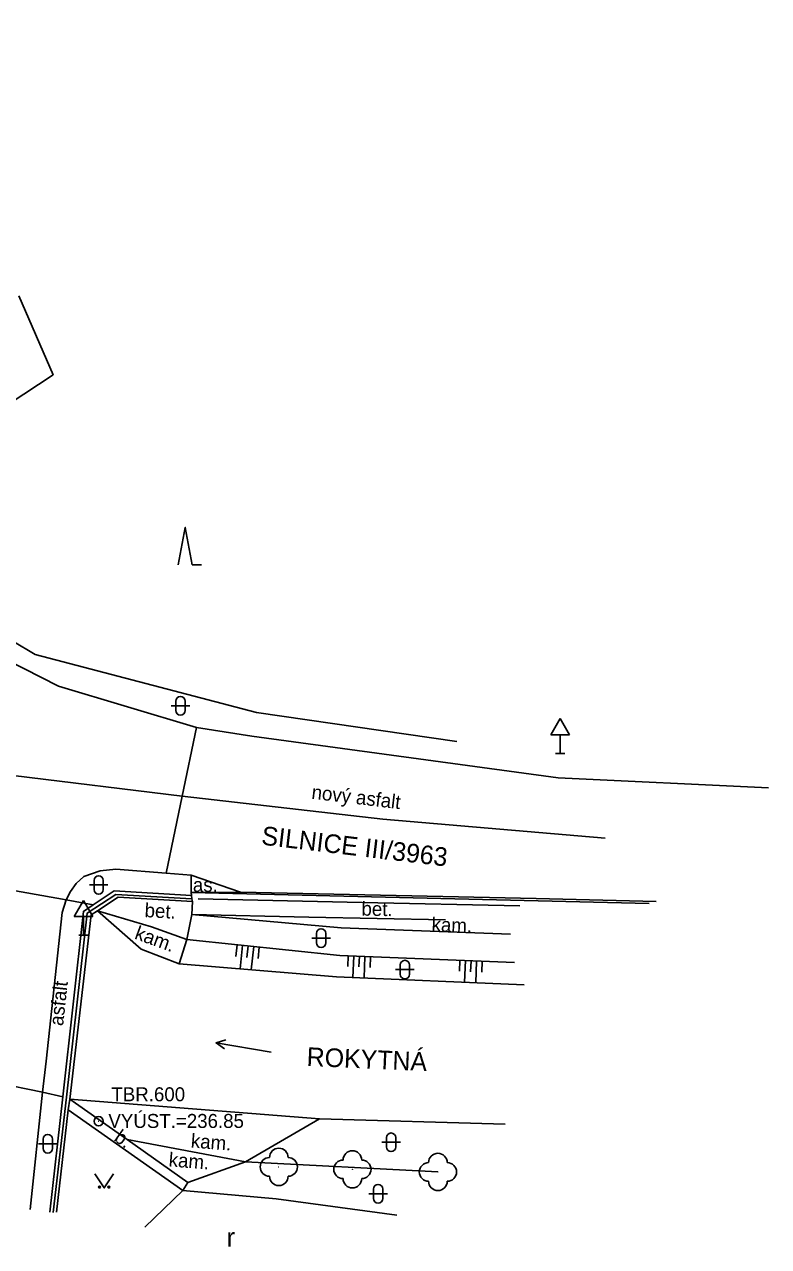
# Model space of a CAD drawing. Extents: x -621335 to -621199, y -1175437 to -1175180.
# Drawn here: x -621239.4 to -621199.5, y -1175433.3 to -1175367.7 of the extents above; entities that cross this region are included whole.
import ezdxf

# ---------------------------------------------------------------- set-up
doc = ezdxf.new("R2010")
doc.units = 0
for name, color, linetype in [('Budovy - zadní trakty', 7, 'Continuous'), ('Doplňkové značky', 7, 'Continuous'), ('Názvy', 7, 'Continuous'), ('Pomocné popisy', 7, 'Continuous'), ('Rozhraní ploch', 7, 'Continuous'), ('Výškopis', 7, 'Continuous'), ('Zeleň', 7, 'Continuous'), ('Značky kultur', 7, 'Continuous')]:
    doc.layers.add(name, color=color, linetype=linetype)

msp = doc.modelspace()

# ---------------------------------------------------------------- linework, layer by layer
at = {"layer": 'Budovy - zadní trakty'}
msp.add_lwpolyline([(-621247.56, -1175392.9), (-621247.26, -1175392.7), (-621237.86, -1175386.5), (-621239.7, -1175382.27)], dxfattribs=at)
at = {"layer": 'Doplňkové značky'}
for p, q in [((-621210.63, -1175404.944), (-621211.13, -1175405.81)), ((-621210.63, -1175404.944), (-621210.13, -1175405.81)), ((-621211.13, -1175405.81), (-621210.13, -1175405.81)), ((-621210.63, -1175406.81), (-621210.63, -1175405.81)), ((-621210.88, -1175406.81), (-621210.38, -1175406.81)), ((-621205.86, -1175414.86), (-621230.45, -1175414.28)), ((-621236.22, -1175414.694), (-621236.72, -1175415.56)), ((-621236.22, -1175414.694), (-621235.72, -1175415.56)), ((-621236.72, -1175415.56), (-621235.72, -1175415.56)), ((-621236.22, -1175416.56), (-621236.22, -1175415.56)), ((-621236.47, -1175416.56), (-621235.97, -1175416.56))]:
    msp.add_line(p, q, dxfattribs=at)
for points in [[(-621230.43, -1175414.44), (-621234.58, -1175414.18), (-621235.7, -1175414.93), (-621236.23, -1175415.29), (-621237.34, -1175425.23), (-621238.03, -1175431.41)], [(-621230.4, -1175414.62), (-621234.49, -1175414.38), (-621236.02, -1175415.38), (-621237.14, -1175425.25), (-621237.86, -1175431.43)], [(-621237.68, -1175431.42), (-621237.04, -1175425.93), (-621236.96, -1175425.35), (-621235.81, -1175415.47), (-621235.48, -1175415.26), (-621234.36, -1175414.53), (-621230.38, -1175414.75)], [(-621230.38, -1175414.75), (-621230.4, -1175414.62), (-621230.43, -1175414.44)], [(-621230.06, -1175414.62), (-621221.26, -1175414.8), (-621212.81, -1175414.98)], [(-621230.62, -1175429.83), (-621233.88, -1175427.52), (-621236.96, -1175425.35)], [(-621230.62, -1175429.83), (-621230.89, -1175430.26), (-621237.04, -1175425.93)]]:
    msp.add_lwpolyline(points, dxfattribs=at)
for radius in [0.25, 0.0005]:
    msp.add_circle((-621235.41, -1175426.54), radius, dxfattribs=at)
at = {"layer": 'Rozhraní ploch'}
for p, q in [((-621237.16, -1175414.66), (-621246.24, -1175413.05)), ((-621231.78, -1175413.24), (-621230.45, -1175413.35)), ((-621230.45, -1175413.35), (-621227.8, -1175414.26)), ((-621230.45, -1175414.28), (-621227.8, -1175414.26)), ((-621235.7, -1175414.93), (-621237.16, -1175414.66)), ((-621230.41, -1175415.46), (-621230.38, -1175414.75)), ((-621230.67, -1175416.8), (-621230.41, -1175415.46)), ((-621231.08, -1175418.1), (-621230.67, -1175416.8)), ((-621247.33, -1175423.15), (-621238.43, -1175424.99)), ((-621239.09, -1175431.27), (-621238.43, -1175424.99)), ((-621238.43, -1175424.99), (-621237.34, -1175425.23)), ((-621236.96, -1175425.35), (-621223.55, -1175426.41)), ((-621223.55, -1175426.41), (-621227.53, -1175428.72)), ((-621223.55, -1175426.41), (-621213.59, -1175426.69)), ((-621227.53, -1175428.72), (-621233.88, -1175427.52)), ((-621227.53, -1175428.72), (-621230.62, -1175429.83))]:
    msp.add_line(p, q, dxfattribs=at)
for points in [[(-621289.26, -1175328.38), (-621284.69, -1175342.49), (-621282.48, -1175348.71), (-621278.54, -1175359.18), (-621274.2, -1175369.3), (-621270.32, -1175376.95), (-621266.97, -1175382.2), (-621259.66, -1175391.26), (-621249.09, -1175401.63), (-621240, -1175407.99), (-621230.92, -1175409.11)], [(-621249.92, -1175395.65), (-621246.88, -1175398.47), (-621237.56, -1175403.21), (-621230.15, -1175405.43)], [(-621230.15, -1175405.43), (-621230.92, -1175409.11), (-621231.78, -1175413.24)], [(-621230.15, -1175405.43), (-621227.18, -1175405.88), (-621210.75, -1175408.13), (-621199.45, -1175408.65)], [(-621230.92, -1175409.11), (-621220.16, -1175410.34), (-621208.23, -1175411.36)], [(-621237.16, -1175414.66), (-621236.92, -1175414.21), (-621236.61, -1175413.79), (-621236.21, -1175413.41), (-621235.33, -1175413.11), (-621234.49, -1175413.02), (-621231.78, -1175413.24)], [(-621230.43, -1175414.44), (-621230.45, -1175414.28), (-621230.45, -1175413.35)], [(-621227.8, -1175414.26), (-621211.92, -1175414.59), (-621205.48, -1175414.75)], [(-621238.43, -1175424.99), (-621238.22, -1175423.31), (-621237.36, -1175415.35), (-621237.16, -1175414.66)], [(-621231.08, -1175418.1), (-621233.12, -1175417.32), (-621235.48, -1175415.26)], [(-621230.67, -1175416.8), (-621232.58, -1175416.11), (-621235.48, -1175415.26)], [(-621230.41, -1175415.46), (-621224.12, -1175415.59), (-621216.8, -1175415.74)], [(-621213.31, -1175416.5), (-621222.4, -1175416.16), (-621230.41, -1175415.46)], [(-621212.57, -1175419.23), (-621222.64, -1175418.79), (-621231.08, -1175418.1)]]:
    msp.add_lwpolyline(points, dxfattribs=at)
at = {"layer": 'Výškopis'}
for p, q in [((-621227.984, -1175417.078), (-621228.05, -1175417.71)), ((-621227.686, -1175417.109), (-621227.816, -1175418.367)), ((-621227.388, -1175417.14), (-621227.452, -1175417.766)), ((-621227.089, -1175417.171), (-621227.218, -1175418.416)), ((-621226.791, -1175417.202), (-621226.855, -1175417.821)), ((-621222.014, -1175417.668), (-621222.038, -1175418.242)), ((-621221.715, -1175417.681), (-621221.761, -1175418.828)), ((-621221.415, -1175417.693), (-621221.438, -1175418.267)), ((-621221.115, -1175417.705), (-621221.162, -1175418.855)), ((-621220.815, -1175417.717), (-621220.839, -1175418.292)), ((-621216.019, -1175417.911), (-621216.043, -1175418.494)), ((-621215.719, -1175417.923), (-621215.767, -1175419.09)), ((-621215.42, -1175417.935), (-621215.443, -1175418.519)), ((-621215.12, -1175417.947), (-621215.167, -1175419.117)), ((-621214.82, -1175417.96), (-621214.844, -1175418.545)), ((-621227.53, -1175428.72), (-621217.2, -1175429.26))]:
    msp.add_line(p, q, dxfattribs=at)
msp.add_lwpolyline([(-621230.67, -1175416.8), (-621222.47, -1175417.65), (-621213.08, -1175418.03)], dxfattribs=at)
at = {"layer": 'Zeleň'}
msp.add_line((-621230.89, -1175430.26), (-621232.93, -1175432.23), dxfattribs=at)
for points in [[(-621247.75, -1175395.27), (-621246.03, -1175397.22), (-621238.82, -1175401.51)], [(-621238.82, -1175401.51), (-621226.93, -1175404.61), (-621216.19, -1175406.17)], [(-621230.89, -1175430.26), (-621225.89, -1175430.7), (-621219.4, -1175431.58)]]:
    msp.add_lwpolyline(points, dxfattribs=at)
for centre in [(-621225.74, -1175428.99), (-621221.79, -1175429.12), (-621217.2, -1175429.26)]:
    msp.add_circle(centre, 0.0005, dxfattribs=at)
for centre, start, end in [((-621225.74, -1175428.49), 0, 179.99999), ((-621221.79, -1175428.62), 0, 179.99999), ((-621226.24, -1175428.99), 89.99999, 269.99999), ((-621225.24, -1175428.99), 270, 89.99999), ((-621222.29, -1175429.12), 89.99999, 269.99999), ((-621221.29, -1175429.12), 270, 89.99999), ((-621217.7, -1175429.26), 89.99999, 269.99999), ((-621217.2, -1175428.76), 0, 179.99999), ((-621216.7, -1175429.26), 270, 89.99999), ((-621225.74, -1175429.49), 179.99999, 359.99999), ((-621221.79, -1175429.62), 179.99999, 359.99999), ((-621217.2, -1175429.76), 179.99999, 359.99999)]:
    msp.add_arc(centre, 0.5, start, end, dxfattribs=at)
at = {"layer": 'Značky kultur'}
for p, q in [((-621231.52, -1175404.26), (-621230.52, -1175404.26)), ((-621231.27, -1175404.51), (-621231.27, -1175404.01)), ((-621230.77, -1175404.51), (-621230.77, -1175404.01)), ((-621235.66, -1175414.12), (-621235.66, -1175413.62)), ((-621235.16, -1175414.12), (-621235.16, -1175413.62)), ((-621235.91, -1175413.87), (-621234.91, -1175413.87)), ((-621223.97, -1175416.72), (-621222.97, -1175416.72)), ((-621223.72, -1175416.97), (-621223.72, -1175416.47)), ((-621223.22, -1175416.97), (-621223.22, -1175416.47)), ((-621219.22, -1175418.66), (-621219.22, -1175418.16)), ((-621218.72, -1175418.66), (-621218.72, -1175418.16)), ((-621219.47, -1175418.41), (-621218.47, -1175418.41)), ((-621226.15, -1175422.83), (-621229.109, -1175422.336)), ((-621219.96, -1175427.92), (-621219.96, -1175427.42)), ((-621219.46, -1175427.92), (-621219.46, -1175427.42)), ((-621238.64, -1175427.75), (-621237.64, -1175427.75)), ((-621238.39, -1175428), (-621238.39, -1175427.5)), ((-621237.89, -1175428), (-621237.89, -1175427.5)), ((-621220.21, -1175427.67), (-621219.21, -1175427.67)), ((-621220.91, -1175430.43), (-621219.91, -1175430.43)), ((-621220.66, -1175430.68), (-621220.66, -1175430.18)), ((-621220.16, -1175430.68), (-621220.16, -1175430.18))]:
    msp.add_line(p, q, dxfattribs=at)
for points in [[(-621231.135, -1175396.69), (-621230.76, -1175394.69), (-621230.385, -1175396.69), (-621229.885, -1175396.69)], [(-621228.657, -1175422.665), (-621229.109, -1175422.336), (-621228.575, -1175422.172)], [(-621235.61, -1175429.37), (-621235.11, -1175430.12), (-621234.61, -1175429.37)]]:
    msp.add_lwpolyline(points, dxfattribs=at)
for centre in [(-621235.36, -1175430.07), (-621234.86, -1175430.07)]:
    msp.add_circle(centre, 0.05, dxfattribs=at)
for centre, start, end in [((-621231.02, -1175404.01), 0, 179.99999), ((-621231.02, -1175404.51), 179.99999, 359.99999), ((-621235.41, -1175413.62), 0, 179.99999), ((-621235.41, -1175414.12), 179.99999, 359.99999), ((-621223.47, -1175416.47), 0, 179.99999), ((-621223.47, -1175416.97), 179.99999, 359.99999), ((-621218.97, -1175418.16), 0, 179.99999), ((-621218.97, -1175418.66), 179.99999, 359.99999), ((-621238.14, -1175427.5), 0, 179.99999), ((-621219.71, -1175427.42), 0, 179.99999), ((-621238.14, -1175428), 179.99999, 359.99999), ((-621219.71, -1175427.92), 179.99999, 359.99999), ((-621220.41, -1175430.18), 0, 179.99999), ((-621220.41, -1175430.68), 179.99999, 359.99999)]:
    msp.add_arc(centre, 0.25, start, end, dxfattribs=at)

# ---------------------------------------------------------------- texts
at = {"layer": 'Názvy'}
for s, rotation, p in [('SILNICE III/3963', 353.24493, (-621226.71, -1175411.7)), ('ROKYTNÁ', 357.5, (-621224.26, -1175423.57))]:
    msp.add_text(s, height=1, rotation=rotation, dxfattribs=at).set_placement(p)
at = {"layer": 'Pomocné popisy'}
for s, rotation, p in [('nový asfalt', 353.24493, (-621224.01, -1175409.24)), ('as.', 0.43241, (-621230.35, -1175414.24)), ('bet.', 356.83612, (-621232.96, -1175415.59)), ('bet.', 358.82607, (-621221.31, -1175415.51)), ('kam.', 357.86, (-621217.55, -1175416.35)), ('kam.', 340.14, (-621233.53, -1175416.74)), ('asfalt', 83.84, (-621237.32, -1175421.45)), ('b.', 324.85, (-621234.64, -1175427.55)), ('kam.', 355.48042, (-621230.482, -1175427.947)), ('kam.', 355.48042, (-621231.67, -1175428.96))]:
    msp.add_text(s, height=0.75, rotation=rotation, dxfattribs=at).set_placement(p)
for s, p in [('TBR.600', (-621234.727, -1175425.47)), ('VYÚST.=236.85', (-621234.887, -1175426.9))]:
    msp.add_text(s, height=0.75, dxfattribs=at).set_placement(p)
at = {"layer": 'Značky kultur'}
msp.add_text('r', height=1, dxfattribs=at).set_placement((-621228.538, -1175433.262))

doc.saveas('drawing.dxf')
